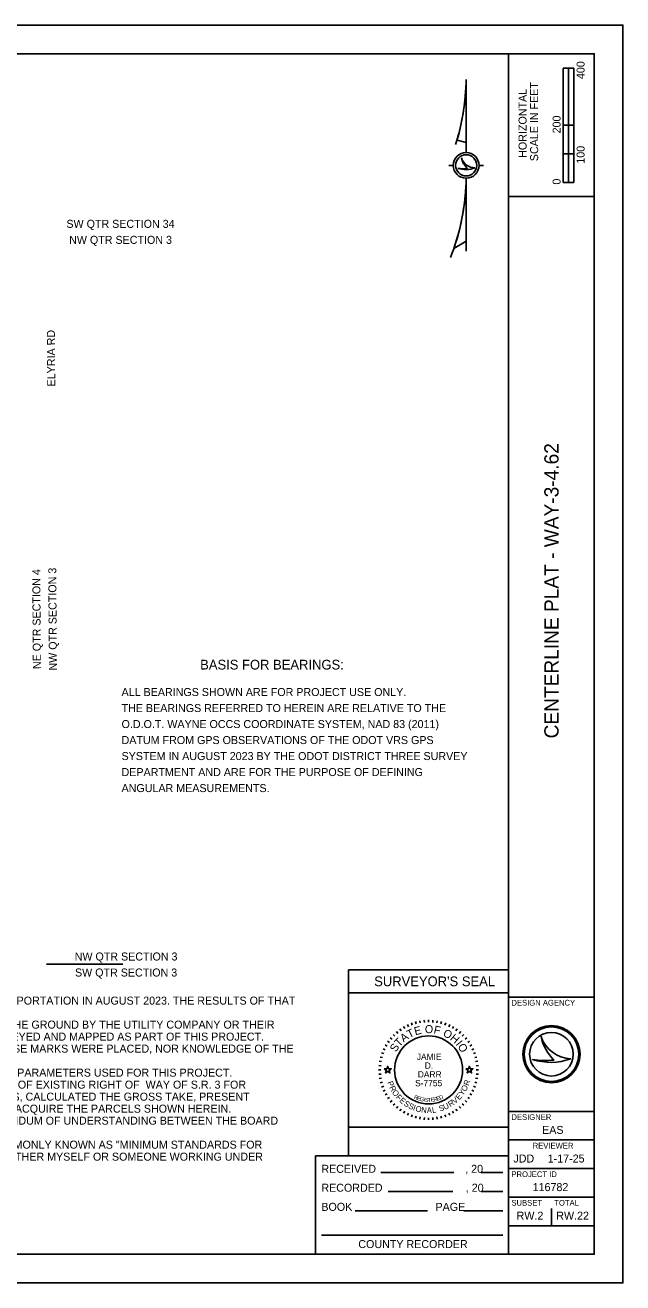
# Model space of a CAD drawing. Extents: x 116796 to 123596, y 461507 to 465907.
# Drawn here: x 121504 to 123596, y 461507 to 465907 of the extents above; entities that cross this region are included whole.
import ezdxf

# ---------------------------------------------------------------- set-up
doc = ezdxf.new("R2010")
doc.units = 0
for name, color, linetype in [('Default', 7, 'Continuous'), ('GE_X_Alignment', 7, 'Continuous'), ('RW_X_Esmt_SH', 7, 'Continuous'), ('SC_Scratch1', 7, 'Continuous'), ('SC_Scratch3', 7, 'Continuous'), ('SV_P_Control_Cells_Set', 7, 'Continuous')]:
    doc.layers.add(name, color=color, linetype=linetype)

msp = doc.modelspace()

# ---------------------------------------------------------------- linework, layer by layer
at = {"layer": 'Default'}
for points in [[(122760.6, 462255.5), (122770, 462255.5), (122772.9, 462264.4), (122775.8, 462255.5), (122785.2, 462255.5), (122777.6, 462250), (122780.5, 462241.1), (122772.9, 462246.6), (122765.3, 462241.1), (122768.2, 462250)], [(123046.6, 462255.5), (123056, 462255.5), (123058.9, 462264.4), (123061.8, 462255.5), (123071.2, 462255.5), (123063.6, 462250), (123066.5, 462241.1), (123058.9, 462246.6), (123051.3, 462241.1), (123054.2, 462250)]]:
    msp.add_lwpolyline(points, close=True, dxfattribs=at)
at = {"layer": 'GE_X_Alignment'}
msp.add_line((121578.7, 462621.6), (121845.7, 462621.6), dxfattribs=at)
at = {"layer": 'RW_X_Esmt_SH'}
for p, q in [((123195.9, 461606.7), (123195.9, 465806.7)), ((123195.9, 465306.7), (123495.9, 465306.7)), ((123195.9, 462506.7), (123495.9, 462506.7)), ((123195.9, 462106.7), (123495.9, 462106.7)), ((123195.9, 462006.7), (123495.9, 462006.7)), ((123195.9, 461906.7), (123495.9, 461906.7)), ((123195.9, 461806.7), (123495.9, 461806.7)), ((123195.9, 461706.7), (123495.9, 461706.7))]:
    msp.add_line(p, q, dxfattribs=at)
msp.add_lwpolyline([(117095.9, 465806.7), (123495.9, 465806.7), (123495.9, 461606.7), (117095.9, 461606.7)], close=True, dxfattribs=at)
at = {"layer": 'SC_Scratch1'}
msp.add_lwpolyline([(116795.9, 461506.7), (123595.9, 461506.7), (123595.9, 465906.7), (116795.9, 465906.7)], close=True, dxfattribs=at)
at = {"layer": 'SC_Scratch3'}
for p, q in [((123387.2, 465356.7), (123387.2, 465756.7)), ((123424.7, 465756.7), (123387.2, 465756.7)), ((123387.2, 465556.7), (123387.2, 465756.7)), ((123387.2, 465756.7), (123405.9, 465756.7)), ((123405.9, 465756.7), (123406, 465756.7)), ((123406, 465756.7), (123406, 465556.7)), ((123424.7, 465756.7), (123424.7, 465356.7)), ((123047.4, 465461.2), (123047.4, 465716.2)), ((123406, 465556.7), (123387.2, 465556.7)), ((123424.5, 465556.7), (123405.9, 465556.7)), ((123405.9, 465556.7), (123405.9, 465456.7)), ((123424.5, 465456.7), (123424.5, 465556.7)), ((123015.5, 465504.3), (123047.4, 465495.6)), ((123405.9, 465456.7), (123387.2, 465456.7)), ((123387.2, 465456.7), (123387.2, 465356.7)), ((123405.9, 465456.7), (123424.5, 465456.7)), ((123405.9, 465356.7), (123405.9, 465456.7)), ((122986.4, 465416.2), (123002.4, 465416.2)), ((123092.4, 465416.2), (123108.4, 465416.2)), ((123047.4, 465116.2), (123047.4, 465371.2)), ((123424.7, 465356.7), (123387.2, 465356.7)), ((123387.2, 465356.7), (123405.9, 465356.7)), ((123047.4, 465151.2), (123004.5, 465125.5)), ((123195.9, 462601.5), (122635.9, 462601.5)), ((122635.9, 462601.5), (122635.9, 461951.5)), ((123195.9, 461951.5), (123195.9, 462601.5)), ((123195.9, 462521.5), (122635.9, 462521.5)), ((122828.4, 462403.1), (122832.4, 462396.2)), ((122841.9, 462410.1), (122845.3, 462402.9)), ((122856, 462416), (122858.8, 462408.5)), ((122870.6, 462420.6), (122872.7, 462412.8)), ((122885.5, 462423.9), (122886.9, 462416)), ((122900.6, 462425.9), (122901.3, 462417.9)), ((122915.9, 462426.5), (122915.9, 462418.5)), ((122931.1, 462425.9), (122930.4, 462417.9)), ((122946.3, 462423.9), (122944.9, 462416)), ((122961.2, 462420.6), (122959.1, 462412.8)), ((122975.7, 462416), (122973, 462408.5)), ((122989.8, 462410.1), (122986.5, 462402.9)), ((123003.4, 462403.1), (122999.4, 462396.2)), ((122781.8, 462364), (122788, 462358.9)), ((122792.1, 462375.3), (122797.8, 462369.6)), ((122803.4, 462385.6), (122808.5, 462379.5)), ((122815.5, 462394.9), (122820.1, 462388.3)), ((123016.3, 462394.9), (123011.7, 462388.3)), ((123028.4, 462385.6), (123023.2, 462379.5)), ((123039.6, 462375.3), (123034, 462369.6)), ((123049.9, 462364), (123043.8, 462358.9)), ((123309.4, 462368.6), (123309.4, 462368.6)), ((122751.4, 462311.4), (122759, 462308.6)), ((122757.3, 462325.5), (122764.5, 462322.1)), ((122764.3, 462339), (122771.3, 462335)), ((122772.5, 462351.9), (122779.1, 462347.3)), ((123059.2, 462351.9), (123052.7, 462347.3)), ((123067.4, 462339), (123060.5, 462335)), ((123074.5, 462325.5), (123067.2, 462322.1)), ((123080.3, 462311.4), (123072.8, 462308.6)), ((122741.5, 462266.8), (122749.5, 462266.1)), ((122743.5, 462281.9), (122751.4, 462280.5)), ((122746.8, 462296.8), (122754.6, 462294.8)), ((123084.9, 462296.8), (123077.2, 462294.8)), ((123088.2, 462281.9), (123080.3, 462280.5)), ((123090.2, 462266.8), (123082.2, 462266.1)), ((123279.3, 462288.6), (123279.3, 462288.6)), ((123345.9, 462306.7), (123345.9, 462306.7)), ((123413.3, 462290.4), (123413.3, 462290.4)), ((122740.9, 462251.5), (122748.9, 462251.5)), ((122741.5, 462236.3), (122749.5, 462237)), ((122743.5, 462221.1), (122751.4, 462222.5)), ((123088.2, 462221.1), (123080.3, 462222.5)), ((123090.2, 462236.3), (123082.2, 462237)), ((123090.9, 462251.5), (123082.9, 462251.5)), ((122746.8, 462206.2), (122754.6, 462208.3)), ((122751.4, 462191.7), (122759, 462194.4)), ((122757.3, 462177.6), (122764.5, 462181)), ((123074.5, 462177.6), (123067.2, 462181)), ((123080.3, 462191.7), (123072.8, 462194.4)), ((123084.9, 462206.2), (123077.2, 462208.3)), ((122764.3, 462164), (122771.3, 462168)), ((122772.5, 462151.2), (122779.1, 462155.7)), ((122781.8, 462139), (122788, 462144.2)), ((122792.1, 462127.8), (122797.8, 462133.4)), ((123039.6, 462127.8), (123034, 462133.4)), ((123049.9, 462139), (123043.8, 462144.2)), ((123059.2, 462151.2), (123052.7, 462155.7)), ((123067.4, 462164), (123060.5, 462168)), ((122803.4, 462117.5), (122808.5, 462123.6)), ((122815.5, 462108.2), (122820.1, 462114.7)), ((122828.4, 462100), (122832.4, 462106.9)), ((122841.9, 462092.9), (122845.3, 462100.2)), ((122856, 462087.1), (122858.8, 462094.6)), ((122870.6, 462082.5), (122872.7, 462090.2)), ((122961.2, 462082.5), (122959.1, 462090.2)), ((122975.7, 462087.1), (122973, 462094.6)), ((122989.8, 462092.9), (122986.5, 462100.2)), ((123003.4, 462100), (122999.4, 462106.9)), ((123016.3, 462108.2), (123011.7, 462114.7)), ((123028.4, 462117.5), (123023.2, 462123.6)), ((122885.5, 462079.2), (122886.9, 462087.1)), ((122900.6, 462077.2), (122901.3, 462085.2)), ((122915.9, 462076.5), (122915.9, 462084.5)), ((122931.1, 462077.2), (122930.4, 462085.2)), ((122946.3, 462079.2), (122944.9, 462087.1)), ((123195.9, 461951.5), (122635.9, 461951.5)), ((123345.9, 461706.7), (123345.9, 461766.7))]:
    msp.add_line(p, q, dxfattribs=at)
for points in [[(123015.3, 465504.4), (123015.5, 465504.3), (123047.4, 465495.6), (123047.4, 465716.2)], [(123004.5, 465125.5), (123047.4, 465151.2), (123047.4, 465371.2)]]:
    msp.add_lwpolyline(points, dxfattribs=at)
msp.add_lwpolyline([(123195.9, 461951.5), (123195.9, 462051.5), (122635.9, 462051.5), (122635.9, 461951.5)], close=True, dxfattribs=at)
for centre, radius in [((123047.4, 465416.2), 45), ((123047.4, 465416.2), 37), ((123345.9, 462306.7), 100), ((123345.9, 462306.7), 95.4), ((123345.9, 462306.7), 95.4), ((122915.9, 462251.5), 119), ((123345.9, 462306.7), 76.4)]:
    msp.add_circle(centre, radius, dxfattribs=at)
for centre, radius, start, end in [((122258.9, 465727.3), 788.5, 342.4153, 359.1947), ((122258.9, 465727.3), 788.5, 343.5754, 359.1947), ((123078.9, 465458.8), 51, 199.1575, 269.3709), ((123100.6, 465458), 71.7, 192.8556, 227.3141), ((123045.2, 465492), 90.5, 252.4874, 291.486), ((123036.4, 465518.5), 114.3, 260.7277, 277.8734), ((122258.9, 465382.3), 788.5, 338.5054, 359.1947), ((122258.9, 465382.3), 788.5, 340.9936, 359.1947), ((123419.1, 462406.2), 116, 198.9257, 198.9319), ((123465.2, 462400.7), 159.1, 191.6379, 191.6421), ((123419.1, 462406.2), 116, 198.9319, 267.1657), ((123465.2, 462400.7), 159.1, 191.6421, 226.0947), ((123343.8, 462480.7), 202.6, 251.4576, 290.0832), ((123325.5, 462537.6), 253.2, 259.4964, 259.4995), ((123343.8, 462480.7), 202.6, 251.4527, 251.4576), ((123325.5, 462537.6), 253.2, 259.4995, 276.6672)]:
    msp.add_arc(centre, radius, start, end, dxfattribs=at)
at = {"layer": 'SV_P_Control_Cells_Set'}
for p, q in [((122520.6, 461606.7), (122520.6, 461951.5)), ((122520.6, 461951.5), (123195.9, 461951.5)), ((123195.9, 461951.5), (123195.9, 461606.7)), ((122749.2, 461892.5), (123003.7, 461892.5)), ((123100.4, 461892.5), (123175.9, 461892.5)), ((122774.3, 461825.9), (123000.5, 461825.9)), ((123100.4, 461825.9), (123175.9, 461825.9)), ((122658.5, 461759.2), (122911.7, 461759.2)), ((123039.7, 461759.2), (123175.9, 461759.2)), ((122540.6, 461673.6), (123175.9, 461673.6))]:
    msp.add_line(p, q, dxfattribs=at)

# ---------------------------------------------------------------- texts
at = {"layer": 'Default'}
for s, p in [('I, JAMIE D. DARR, P.S. HAVE CONDUCTED A SURVEY OF THE EXISTING CONDITIONS FOR THE OHIO DEPARTMENT OF TRANSPORTATION IN AUGUST 2023. THE RESULTS OF THAT', (119187.6, 462480.1)), ('UNDERGROUND UTILITY LOCATIONS ARE SHOWN FOR INFORMATION PURPOSES ONLY. THEIR LOCATION AS MARKED ON THE GROUND BY THE UTILITY COMPANY OR THEIR', (119187.6, 462396.1)), ('REPRESENTATIVES PER OHIO811 CONFIRMATION NUMBERS B319100751-00B,B319100756-00B AND B319100742 WERE SURVEYED AND MAPPED AS PART OF THIS PROJECT.', (119187.6, 462354.1)), ('I FOLLOWED OHIO811 UTILITY DAMAGE PREVENTION LAWS AND HAVE NO DIRECT KNOWLEDGE OR CONTROL OF HOW THESE MARKS WERE PLACED, NOR KNOWLEDGE OF THE ', (119187.6, 462312.1)), ('SEE THE AFFIXED SURVEY PARAMETERS NOTE ON THE CENTERLINE PLATS FOR THE HORIZONTAL AND VERTICAL SURVEY PARAMETERS USED FOR THIS PROJECT.', (119187.6, 462228.1)), ('AS PART OF THIS PROJECT I HAVE REESTABLISHED THE LOCATIONS OF THE EXISTING BOUNDARY LINES AND CENTERLINE OF EXISTING RIGHT OF  WAY OF S.R. 3 FOR', (119187.6, 462186.1)), ('PROPERTY TAKES CONTAINED HEREIN. AS PART OF THIS PROJECT I HAVE ESTABLISHED THE PROPOSED BOUNDARY LINES, CALCULATED THE GROSS TAKE, PRESENT', (119187.6, 462144.1)), ('AS PART OF THIS WORK, RIGHT OF WAY MONUMENTS WILL BE SET AT THE LOCATIONS SHOWN HEREIN PER THE MEMORANDUM OF UNDERSTANDING BETWEEN THE BOARD', (119187.6, 462060.1)), ('ROAD OCCUPIED (PRO), NET TAKE, AND NET RESIDUE; AS WELL AS PREPARED THE LEGAL DESCRIPTIONS NECESSARY TO ACQUIRE THE PARCELS SHOWN HEREIN.', (119187.6, 462102.1)), ('ALL OF MY WORK CONTAINED HEREIN WAS CONDUCTED IN ACCORDANCE WITH OHIO ADMINISTRATIVE CODE 4733-37 COMMONLY KNOWN AS "MINIMUM STANDARDS FOR', (119187.6, 461976.1)), ('BOUNDARY SURVEYS IN THE STATE OF OHIO" UNLESS SO NOTED. THE WORDS I AND MY AS USED HEREIN ARE TO MEAN EITHER MYSELF OR SOMEONE WORKING UNDER', (119187.6, 461934.1))]:
    msp.add_text(s, height=28, dxfattribs=at).set_placement(p)
at = {"layer": 'GE_X_Alignment'}
msp.add_text('ELYRIA RD', height=28, rotation=90.3623, dxfattribs=at).set_placement((121609.2, 464642.9))
for s, p in [('NW QTR SECTION 3', (121677.2, 462634.4)), ('SW QTR SECTION 3', (121678.3, 462578.4))]:
    msp.add_text(s, height=28, dxfattribs=at).set_placement(p)
at = {"layer": 'SC_Scratch3'}
for s, height, rotation, p in [('400', 28, 90, (123461.9, 465718)), ('SCALE IN FEET', 28, 90, (123299.4, 465430.8)), ('HORIZONTAL', 28, 90, (123258.9, 465442.5)), ('200', 28, 90, (123378, 465528)), ('100', 28, 90, (123461.9, 465422.1)), ('0', 28, 90, (123378, 465348.9)), ('CENTERLINE PLAT - WAY-3-4.62', 50, 90, (123370.9, 463411.4)), ('T', 28, 25.7167, (122848.2, 462361.9)), ('E', 28, 15.7571, (122869.6, 462372.3)), ('O', 28, 359.7812, (122902.8, 462380.4)), ('F', 28, 347.4362, (122932.1, 462379.9)), ('T', 28, 46.4344, (122813.5, 462330.8)), ('A', 28, 36.4747, (122828.6, 462347.2)), ('O', 28, 332.2586, (122963.8, 462371.8)), ('H', 28, 319.9136, (122988.5, 462358.7)), ('I', 28, 308.367, (123009.2, 462341.2)), ('S', 28, 57.1924, (122801.5, 462311.8)), ('O', 28, 303.1491, (123016.3, 462333.3)), ('P', 20, 289.7431, (122770.9, 462208.3)), ('R', 20, 296.9802, (122777.7, 462190.1)), ('O', 20, 304.7158, (122786.5, 462173.1)), ('Y', 20, 55.5058, (123035.9, 462159.5)), ('O', 20, 62.7428, (123045.9, 462174.2)), ('R', 20, 70.983, (123056.1, 462194.9)), ('F', 20, 312.956, (122799.7, 462154.7)), ('E', 20, 319.6885, (122812, 462141.6)), ('S', 20, 326.9255, (122827, 462129.2)), ('S', 20, 334.1626, (122843.1, 462119)), ('R', 14, 334.487, (122863.4, 462152.5)), ('E', 14, 341.04, (122874, 462147.5)), ('G', 14, 347.4752, (122884.2, 462143.9)), ('I', 14, 353.7858, (122897.7, 462140.9)), ('S', 14, 356.8926, (122903, 462140.1)), ('T', 14, 3.0061, (122913, 462139.3)), ('E', 14, 6.0117, (122923.7, 462139.8)), ('R', 14, 11.9184, (122934.4, 462141)), ('E', 14, 17.6836, (122945.8, 462143.6)), ('D', 14, 23.3052, (122956.1, 462146.9)), ('U', 20, 25.5604, (122972.5, 462111.2)), ('R', 20, 33.296, (122992.2, 462121)), ('V', 20, 41.0316, (123008.2, 462131.7)), ('E', 20, 48.2687, (123023.2, 462145)), ('I', 20, 341.3997, (122859.7, 462111.1)), ('O', 20, 345.1351, (122868.2, 462107.9)), ('N', 20, 353.3752, (122889.1, 462102.6)), ('A', 20, 1.1108, (122909.7, 462100.4)), ('L', 20, 8.3479, (122929.2, 462100.9)), ('S', 20, 18.3234, (122956, 462105.7))]:
    msp.add_text(s, height=height, rotation=rotation, dxfattribs=at).set_placement(p)
for s, height, p in [("SURVEYOR'S SEAL", 34, (122725.5, 462544.5)), ('DESIGN AGENCY', 20, (123205.9, 462476.7)), ('JAMIE', 22, (122874.6, 462286.5)), ('D.', 22, (122902.5, 462255.9)), ('DARR', 22, (122878.1, 462225.2)), ('S-7755', 22, (122868.7, 462194.5)), ('DESIGNER', 20, (123205.9, 462076.7)), ('EAS', 28, (123313.3, 462027.7)), ('REVIEWER', 20, (123280.2, 461976.7)), ('1-17-25', 28, (123332.8, 461927.7)), ('JDD', 28, (123212.7, 461927.7)), ('PROJECT ID', 20, (123205.9, 461876.7)), ('116782', 28, (123280.1, 461827.7)), ('SUBSET', 20, (123205.9, 461776.7)), ('TOTAL', 20, (123355.9, 461776.7)), ('RW.2', 28, (123224, 461727.7)), ('RW.22', 28, (123362.8, 461727.7))]:
    msp.add_text(s, height=height, dxfattribs=at).set_placement(p)
at = {"layer": 'SV_P_Control_Cells_Set'}
for s, height, p in [('SW QTR SECTION 34', 28, (121648.3, 465197.6)), ('NW QTR SECTION 3', 28, (121657.8, 465141.6)), ('BASIS FOR BEARINGS:', 34, (122116.4, 463652.4)), ('ALL BEARINGS SHOWN ARE FOR PROJECT USE ONLY.', 28, (121841.3, 463559.6)), ('THE BEARINGS REFERRED TO HEREIN ARE RELATIVE TO THE ', 28, (121841.3, 463503.6)), ('O.D.O.T. WAYNE OCCS COORDINATE SYSTEM, NAD 83 (2011)', 28, (121841.3, 463447.6)), ('DATUM FROM GPS OBSERVATIONS OF THE ODOT VRS GPS', 28, (121841.3, 463391.6)), ('SYSTEM IN AUGUST 2023 BY THE ODOT DISTRICT THREE SURVEY', 28, (121841.3, 463335.6)), ('DEPARTMENT AND ARE FOR THE PURPOSE OF DEFINING', 28, (121841.3, 463279.6)), ('ANGULAR MEASUREMENTS.', 28, (121841.3, 463223.6)), ('RECEIVED                              , 20', 28, (122540.6, 461891.6)), ('RECORDED                            , 20', 28, (122540.6, 461825.5)), ('BOOK                            PAGE', 28, (122540.6, 461758.6)), ('COUNTY RECORDER', 28, (122670, 461628.3))]:
    msp.add_text(s, height=height, dxfattribs=at).set_placement(p)
for s, p in [('NE QTR SECTION 4', (121558.9, 463654.1)), ('NW QTR SECTION 3', (121615, 463648.8))]:
    msp.add_text(s, height=28, rotation=90.3623, dxfattribs=at).set_placement(p)

doc.saveas('drawing.dxf')
